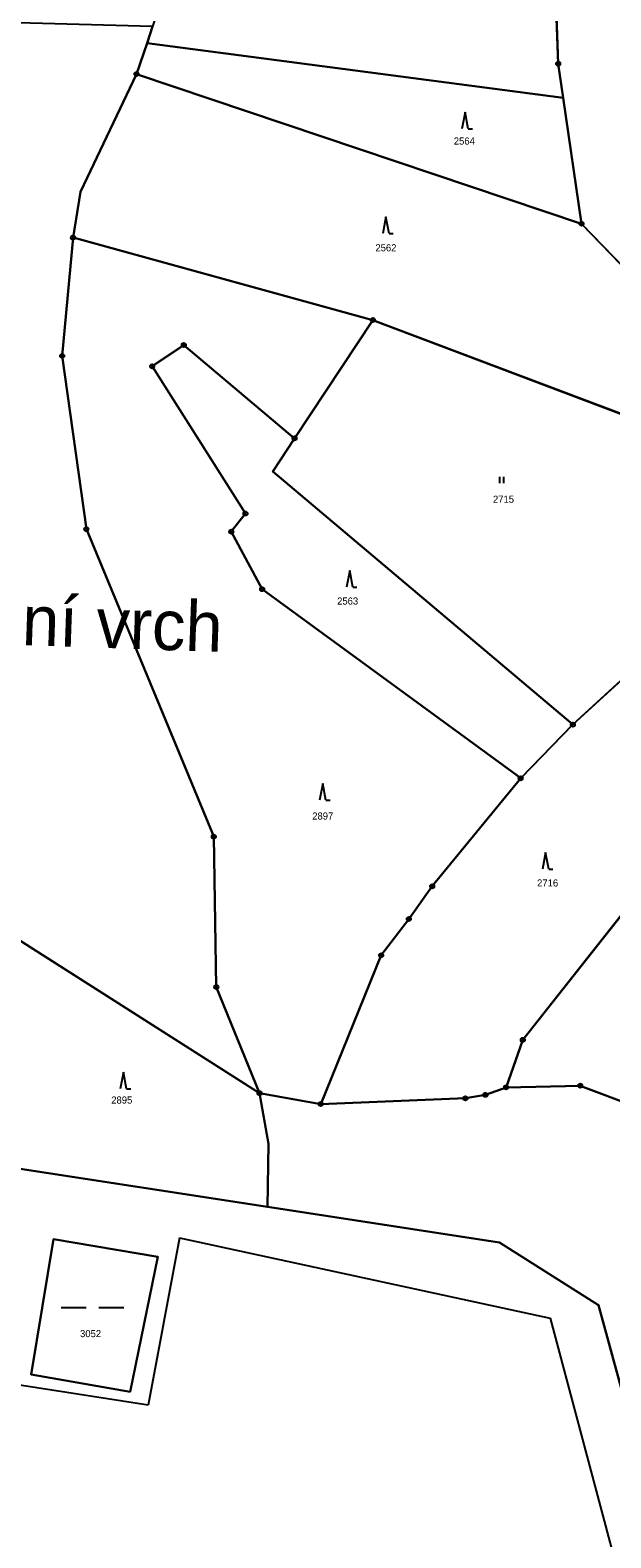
# Model space of a CAD drawing. Extents: x -689422 to -685210, y -987725 to -982160.
# Drawn here: x -687914.3 to -687774.8, y -986923.9 to -986562 of the extents above; entities that cross this region are included whole.
import ezdxf

# ---------------------------------------------------------------- set-up
doc = ezdxf.new("R2010")
doc.units = 0
for name, color, linetype in [('KN_Hranice_parcel', 7, 'Continuous'), ('KN_Hranice_parcel_vnitrni_kresba', 7, 'Continuous'), ('KN_Parcelni cisla', 7, 'Continuous'), ('KN_Polygon parcely', 7, 'Continuous'), ('KN_Popisy_pomistni nazvy', 7, 'Continuous'), ('KN_POZEMKY_LESNI POZEMEK', 7, 'Continuous'), ('KN_POZEMKY_TTP', 7, 'Continuous'), ('KN_POZEMKY_VODNI_PLOCHA', 7, 'Continuous'), ('KN_VYUZITI_10_vodni plocha_nadrz umela', 7, 'Continuous'), ('KN_Značky bodu BP', 7, 'Continuous'), ('KN_Značky kultur', 7, 'Continuous')]:
    doc.layers.add(name, color=color, linetype=linetype)

msp = doc.modelspace()

# ---------------------------------------------------------------- linework, layer by layer
at = {"layer": 'KN_Hranice_parcel'}
for p, q in [((-687884.88, -986561.12), (-687886.23, -986565.1)), ((-687886.23, -986565.1), (-687888.75, -986572.55)), ((-687886.23, -986565.1), (-687786.3, -986578.26)), ((-687781.9, -986608.47), (-687888.75, -986572.55)), ((-687787.49, -986570.08), (-687786.3, -986578.26)), ((-687786.3, -986578.26), (-687781.9, -986608.47)), ((-687781.9, -986608.47), (-687722.74, -986669.66)), ((-687904, -986611.8), (-687832, -986631.6)), ((-687832, -986631.6), (-687850.8, -986660)), ((-687832, -986631.6), (-687755.13, -986660.64)), ((-687783.97, -986728.72), (-687762.96, -986709.43)), ((-687796.5, -986741.6), (-687783.97, -986728.72)), ((-687924.19, -986775.84), (-687859.2, -986817.2)), ((-687844.5, -986819.8), (-687859.2, -986817.2)), ((-687917.71, -986835.19), (-687857.29, -986844.48)), ((-687857.29, -986844.48), (-687801.59, -986853.04))]:
    msp.add_line(p, q, dxfattribs=at)
for points in [[(-687797.83, -986386.92), (-687790.62, -986405.91), (-687786.34, -986436.56), (-687784.88, -986471.18), (-687789.17, -986524.19), (-687787.49, -986570.08)], [(-687888.75, -986572.55), (-687902.18, -986600.85), (-687904, -986611.8)], [(-687859.2, -986817.2), (-687869.6, -986791.7), (-687870.2, -986755.6), (-687900.8, -986681.8), (-687906.6, -986640.2), (-687904, -986611.8)], [(-687850.8, -986660), (-687877.4, -986637.6), (-687885, -986642.7), (-687862.6, -986678.05), (-687866, -986682.4), (-687858.6, -986696.2), (-687796.5, -986741.6)], [(-687850.8, -986660), (-687856.04, -986667.92), (-687783.97, -986728.72)], [(-687796.5, -986741.6), (-687817.75, -986767.54), (-687823.36, -986775.4), (-687830, -986784.1), (-687844.5, -986819.8)], [(-687800, -986815.8), (-687796, -986804.4), (-687745, -986739.8)], [(-687760, -986828.8), (-687769, -986820.4), (-687782.2, -986815.4), (-687800, -986815.8)], [(-687857.29, -986844.48), (-687857.05, -986829.39), (-687859.2, -986817.2)], [(-687800, -986815.8), (-687804.97, -986817.61), (-687809.77, -986818.43), (-687844.5, -986819.8)], [(-687890.28, -986888.85), (-687883.65, -986856.49), (-687908.72, -986852.2), (-687914.04, -986884.71), (-687890.28, -986888.85)], [(-687801.59, -986853.04), (-687777.85, -986868.06), (-687738.9, -987010.24)]]:
    msp.add_lwpolyline(points, dxfattribs=at)
at = {"layer": 'KN_Hranice_parcel_vnitrni_kresba'}
for p, q in [((-687878.47, -986851.93), (-687885.99, -986892.08)), ((-687878.47, -986851.93), (-687789.45, -986871.21)), ((-687789.45, -986871.21), (-687761.64, -986975.47)), ((-687885.99, -986892.08), (-687925.98, -986885.88))]:
    msp.add_line(p, q, dxfattribs=at)
at = {"layer": 'KN_Polygon parcely'}
for points in [[(-687790.62, -986405.91), (-687786.34, -986436.56), (-687784.88, -986471.18), (-687789.17, -986524.19), (-687787.49, -986570.08), (-687786.3, -986578.26), (-687781.9, -986608.47), (-687722.74, -986669.66), (-687718.6, -986669.11), (-687717.65, -986667.57), (-687728.99, -986648.21), (-687730.88, -986571), (-687735.67, -986566.76), (-687746.52, -986430.63), (-687750.35, -986431.59), (-687770.7, -986373.38), (-687759.36, -986370.08), (-687790, -986253.39), (-687797.65, -986255.17), (-687805.09, -986188.05), (-687812.02, -986279.24), (-687801.17, -986347.9), (-687797.83, -986386.92)], [(-687871.04, -986468.74), (-687876.41, -986536.11), (-687884.88, -986561.12), (-687886.23, -986565.1), (-687786.3, -986578.26), (-687787.49, -986570.08), (-687789.17, -986524.19), (-687784.88, -986471.18), (-687786.34, -986436.56), (-687790.62, -986405.91), (-687797.83, -986386.92), (-687864.46, -986388.44), (-687867.38, -986407.55), (-687869.16, -986432.27)], [(-687904, -986611.8), (-687902.18, -986600.85), (-687888.75, -986572.55), (-687886.23, -986565.1), (-687884.88, -986561.12), (-687949.56, -986559.41), (-687948.5, -986613.39), (-687940.02, -986665.46), (-687939.49, -986668.72), (-687976.55, -986661.97), (-688002.05, -986645.15), (-687999.83, -986658.89), (-687996.11, -986675.9), (-687982.65, -986687.78), (-687959.59, -986717.67), (-687931.16, -986761.84), (-687924.19, -986775.84), (-687859.2, -986817.2), (-687869.6, -986791.7), (-687870.2, -986755.6), (-687900.8, -986681.8), (-687906.6, -986640.2)], [(-687886.23, -986565.1), (-687888.75, -986572.55), (-687781.9, -986608.47), (-687786.3, -986578.26)], [(-687888.75, -986572.55), (-687902.18, -986600.85), (-687904, -986611.8), (-687832, -986631.6), (-687755.13, -986660.64), (-687722.74, -986669.66), (-687781.9, -986608.47)], [(-687832, -986631.6), (-687904, -986611.8), (-687906.6, -986640.2), (-687900.8, -986681.8), (-687870.2, -986755.6), (-687869.6, -986791.7), (-687859.2, -986817.2), (-687844.5, -986819.8), (-687830, -986784.1), (-687823.36, -986775.4), (-687817.75, -986767.54), (-687796.5, -986741.6), (-687858.6, -986696.2), (-687866, -986682.4), (-687862.6, -986678.05), (-687885, -986642.7), (-687877.4, -986637.6), (-687850.8, -986660)], [(-687762.96, -986709.43), (-687771.34, -986700.37), (-687771.85, -986686.53), (-687761.77, -986674.42), (-687755.13, -986660.64), (-687832, -986631.6), (-687850.8, -986660), (-687856.04, -986667.92), (-687783.97, -986728.72)], [(-687862.6, -986678.05), (-687866, -986682.4), (-687858.6, -986696.2), (-687796.5, -986741.6), (-687783.97, -986728.72), (-687856.04, -986667.92), (-687850.8, -986660), (-687877.4, -986637.6), (-687885, -986642.7)], [(-687796, -986804.4), (-687745, -986739.8), (-687732.15, -986715.97), (-687762.96, -986709.43), (-687783.97, -986728.72), (-687796.5, -986741.6), (-687817.75, -986767.54), (-687823.36, -986775.4), (-687830, -986784.1), (-687844.5, -986819.8), (-687809.77, -986818.43), (-687804.97, -986817.61), (-687800, -986815.8)], [(-687710.7, -986756.1), (-687745, -986739.8), (-687796, -986804.4), (-687800, -986815.8), (-687782.2, -986815.4), (-687769, -986820.4), (-687760, -986828.8)], [(-687857.29, -986844.48), (-687857.05, -986829.39), (-687859.2, -986817.2), (-687924.19, -986775.84), (-687917.3, -986800.19), (-687916.91, -986829.47), (-687917.71, -986835.19)], [(-687844.5, -986819.8), (-687859.2, -986817.2), (-687857.05, -986829.39), (-687857.29, -986844.48), (-687801.59, -986853.04), (-687777.85, -986868.06), (-687738.9, -987010.24), (-687722.96, -987052.43), (-687720.17, -987051.57), (-687736.81, -987011.46), (-687651.15, -986965.83), (-687665.06, -986948.79), (-687685.35, -986917.93), (-687730.5, -986864.37), (-687744.99, -986846.08), (-687760, -986828.8), (-687769, -986820.4), (-687782.2, -986815.4), (-687800, -986815.8), (-687804.97, -986817.61), (-687809.77, -986818.43)], [(-687890.28, -986888.85), (-687914.04, -986884.71), (-687908.72, -986852.2), (-687883.65, -986856.49)], [(-687890.28, -986888.85), (-687883.65, -986856.49), (-687908.72, -986852.2), (-687914.04, -986884.71)]]:
    msp.add_lwpolyline(points, close=True, dxfattribs=at)
msp.add_lwpolyline([(-687738.9, -987010.24), (-687777.85, -986868.06), (-687801.59, -986853.04), (-687857.29, -986844.48), (-687917.71, -986835.19), (-687921.47, -986834.64), (-688030.54, -986818.6), (-688080.39, -986811.27), (-688085.26, -986813.61), (-688094.78, -986845.97), (-688099.71, -986860.89), (-688113.79, -986903.54), (-688114.98, -986909.18), (-688108.19, -986917.45), (-688106.29, -986919.76), (-688107.71, -986957.91)], dxfattribs=at)
at = {"layer": 'KN_POZEMKY_LESNI POZEMEK'}
for p, q in [((-687787.49, -986570.08), (-687789.17, -986524.19)), ((-687884.88, -986561.12), (-687886.23, -986565.1)), ((-687886.23, -986565.1), (-687888.75, -986572.55)), ((-687888.75, -986572.55), (-687886.23, -986565.1)), ((-687886.23, -986565.1), (-687786.3, -986578.26)), ((-687888.75, -986572.55), (-687902.18, -986600.85)), ((-687902.18, -986600.85), (-687888.75, -986572.55)), ((-687888.75, -986572.55), (-687781.9, -986608.47)), ((-687781.9, -986608.47), (-687888.75, -986572.55)), ((-687786.3, -986578.26), (-687787.49, -986570.08)), ((-687781.9, -986608.47), (-687786.3, -986578.26)), ((-687786.3, -986578.26), (-687781.9, -986608.47)), ((-687902.18, -986600.85), (-687904, -986611.8)), ((-687904, -986611.8), (-687902.18, -986600.85)), ((-687722.74, -986669.66), (-687781.9, -986608.47)), ((-687781.9, -986608.47), (-687722.74, -986669.66)), ((-687904, -986611.8), (-687906.6, -986640.2)), ((-687906.6, -986640.2), (-687904, -986611.8)), ((-687904, -986611.8), (-687832, -986631.6)), ((-687832, -986631.6), (-687904, -986611.8)), ((-687832, -986631.6), (-687850.8, -986660)), ((-687755.13, -986660.64), (-687832, -986631.6)), ((-687877.4, -986637.6), (-687885, -986642.7)), ((-687885, -986642.7), (-687877.4, -986637.6)), ((-687850.8, -986660), (-687877.4, -986637.6)), ((-687877.4, -986637.6), (-687850.8, -986660)), ((-687906.6, -986640.2), (-687900.8, -986681.8)), ((-687900.8, -986681.8), (-687906.6, -986640.2)), ((-687885, -986642.7), (-687862.6, -986678.05)), ((-687862.6, -986678.05), (-687885, -986642.7)), ((-687850.8, -986660), (-687856.04, -986667.92)), ((-687856.04, -986667.92), (-687783.97, -986728.72)), ((-687862.6, -986678.05), (-687866, -986682.4)), ((-687866, -986682.4), (-687862.6, -986678.05)), ((-687900.8, -986681.8), (-687870.2, -986755.6)), ((-687870.2, -986755.6), (-687900.8, -986681.8)), ((-687866, -986682.4), (-687858.6, -986696.2)), ((-687858.6, -986696.2), (-687866, -986682.4)), ((-687858.6, -986696.2), (-687796.5, -986741.6)), ((-687796.5, -986741.6), (-687858.6, -986696.2)), ((-687783.97, -986728.72), (-687762.96, -986709.43)), ((-687783.97, -986728.72), (-687796.5, -986741.6)), ((-687796.5, -986741.6), (-687783.97, -986728.72)), ((-687796.5, -986741.6), (-687817.75, -986767.54)), ((-687817.75, -986767.54), (-687796.5, -986741.6)), ((-687796, -986804.4), (-687745, -986739.8)), ((-687745, -986739.8), (-687796, -986804.4)), ((-687870.2, -986755.6), (-687869.6, -986791.7)), ((-687869.6, -986791.7), (-687870.2, -986755.6)), ((-687817.75, -986767.54), (-687823.36, -986775.4)), ((-687823.36, -986775.4), (-687817.75, -986767.54)), ((-687823.36, -986775.4), (-687830, -986784.1)), ((-687830, -986784.1), (-687823.36, -986775.4)), ((-687859.2, -986817.2), (-687924.19, -986775.84)), ((-687924.19, -986775.84), (-687859.2, -986817.2)), ((-687830, -986784.1), (-687844.5, -986819.8)), ((-687844.5, -986819.8), (-687830, -986784.1)), ((-687869.6, -986791.7), (-687859.2, -986817.2)), ((-687859.2, -986817.2), (-687869.6, -986791.7)), ((-687800, -986815.8), (-687796, -986804.4)), ((-687796, -986804.4), (-687800, -986815.8)), ((-687782.2, -986815.4), (-687800, -986815.8)), ((-687800, -986815.8), (-687782.2, -986815.4)), ((-687769, -986820.4), (-687782.2, -986815.4)), ((-687782.2, -986815.4), (-687769, -986820.4)), ((-687844.5, -986819.8), (-687859.2, -986817.2)), ((-687857.05, -986829.39), (-687859.2, -986817.2)), ((-687859.2, -986817.2), (-687844.5, -986819.8)), ((-687859.2, -986817.2), (-687857.05, -986829.39)), ((-687844.5, -986819.8), (-687809.77, -986818.43)), ((-687809.77, -986818.43), (-687844.5, -986819.8)), ((-687809.77, -986818.43), (-687804.97, -986817.61)), ((-687804.97, -986817.61), (-687809.77, -986818.43)), ((-687804.97, -986817.61), (-687800, -986815.8)), ((-687800, -986815.8), (-687804.97, -986817.61)), ((-687857.29, -986844.48), (-687857.05, -986829.39)), ((-687857.05, -986829.39), (-687857.29, -986844.48)), ((-687917.71, -986835.19), (-687857.29, -986844.48)), ((-687857.29, -986844.48), (-687917.71, -986835.19)), ((-687857.29, -986844.48), (-687801.59, -986853.04)), ((-687801.59, -986853.04), (-687857.29, -986844.48)), ((-687908.72, -986852.2), (-687914.04, -986884.71)), ((-687883.65, -986856.49), (-687908.72, -986852.2)), ((-687801.59, -986853.04), (-687777.85, -986868.06)), ((-687777.85, -986868.06), (-687801.59, -986853.04)), ((-687890.28, -986888.85), (-687883.65, -986856.49)), ((-687777.85, -986868.06), (-687738.9, -987010.24)), ((-687738.9, -987010.24), (-687777.85, -986868.06)), ((-687914.04, -986884.71), (-687890.28, -986888.85))]:
    msp.add_line(p, q, dxfattribs=at)
at = {"layer": 'KN_POZEMKY_TTP'}
for p, q in [((-687789.17, -986524.19), (-687787.49, -986570.08)), ((-687886.23, -986565.1), (-687884.88, -986561.12)), ((-687786.3, -986578.26), (-687886.23, -986565.1)), ((-687787.49, -986570.08), (-687786.3, -986578.26)), ((-687850.8, -986660), (-687832, -986631.6)), ((-687832, -986631.6), (-687755.13, -986660.64)), ((-687856.04, -986667.92), (-687850.8, -986660)), ((-687783.97, -986728.72), (-687856.04, -986667.92)), ((-687762.96, -986709.43), (-687783.97, -986728.72))]:
    msp.add_line(p, q, dxfattribs=at)
at = {"layer": 'KN_POZEMKY_VODNI_PLOCHA'}
for p, q in [((-687914.04, -986884.71), (-687908.72, -986852.2)), ((-687908.72, -986852.2), (-687883.65, -986856.49)), ((-687883.65, -986856.49), (-687890.28, -986888.85)), ((-687890.28, -986888.85), (-687914.04, -986884.71))]:
    msp.add_line(p, q, dxfattribs=at)
at = {"layer": 'KN_VYUZITI_10_vodni plocha_nadrz umela'}
for p, q in [((-687914.04, -986884.71), (-687908.72, -986852.2)), ((-687908.72, -986852.2), (-687883.65, -986856.49)), ((-687883.65, -986856.49), (-687890.28, -986888.85)), ((-687890.28, -986888.85), (-687914.04, -986884.71))]:
    msp.add_line(p, q, dxfattribs=at)
at = {"layer": 'KN_Značky bodu BP'}
for centre, radius in [((-687888.75, -986572.55), 0.5), ((-687888.75, -986572.55), 0.0303), ((-687787.49, -986570.08), 0.5), ((-687787.49, -986570.08), 0.0303), ((-687781.9, -986608.47), 0.5), ((-687781.9, -986608.47), 0.0303), ((-687904, -986611.8), 0.5), ((-687904, -986611.8), 0.0303), ((-687832, -986631.6), 0.5), ((-687832, -986631.6), 0.0303), ((-687877.4, -986637.6), 0.5), ((-687877.4, -986637.6), 0.0303), ((-687906.6, -986640.2), 0.5), ((-687906.6, -986640.2), 0.0303), ((-687885, -986642.7), 0.5), ((-687885, -986642.7), 0.0303), ((-687850.8, -986660), 0.5), ((-687850.8, -986660), 0.0303), ((-687862.6, -986678.05), 0.5), ((-687900.8, -986681.8), 0.5), ((-687862.6, -986678.05), 0.0303), ((-687900.8, -986681.8), 0.0303), ((-687866, -986682.4), 0.5), ((-687866, -986682.4), 0.0303), ((-687858.6, -986696.2), 0.5), ((-687858.6, -986696.2), 0.0303), ((-687783.97, -986728.72), 0.5), ((-687783.97, -986728.72), 0.0303), ((-687796.5, -986741.6), 0.5), ((-687796.5, -986741.6), 0.0303), ((-687870.2, -986755.6), 0.5), ((-687870.2, -986755.6), 0.0303), ((-687817.75, -986767.54), 0.5), ((-687817.75, -986767.54), 0.0303), ((-687823.36, -986775.4), 0.5), ((-687823.36, -986775.4), 0.0303), ((-687830, -986784.1), 0.5), ((-687830, -986784.1), 0.0303), ((-687869.6, -986791.7), 0.5), ((-687869.6, -986791.7), 0.0303), ((-687796, -986804.4), 0.5), ((-687796, -986804.4), 0.0303), ((-687800, -986815.8), 0.5), ((-687782.2, -986815.4), 0.5), ((-687782.2, -986815.4), 0.0303), ((-687859.2, -986817.2), 0.5), ((-687859.2, -986817.2), 0.0303), ((-687809.77, -986818.43), 0.5), ((-687809.77, -986818.43), 0.0303), ((-687804.97, -986817.61), 0.5), ((-687804.97, -986817.61), 0.0303), ((-687800, -986815.8), 0.0303), ((-687844.5, -986819.8), 0.5), ((-687844.5, -986819.8), 0.0303)]:
    msp.add_circle(centre, radius, dxfattribs=at)
at = {"layer": 'KN_Značky kultur'}
for p, q in [((-687809.85, -986581.67), (-687810.6, -986585.67)), ((-687809.1, -986585.67), (-687809.85, -986581.67)), ((-687809.1, -986585.67), (-687808.1, -986585.67)), ((-687828.86, -986606.84), (-687829.61, -986610.84)), ((-687828.11, -986610.84), (-687828.86, -986606.84)), ((-687828.11, -986610.84), (-687827.11, -986610.84)), ((-687801.51, -986670.77), (-687801.51, -986669.27)), ((-687800.51, -986670.77), (-687800.51, -986669.27)), ((-687837.56, -986691.73), (-687838.31, -986695.73)), ((-687836.81, -986695.73), (-687837.56, -986691.73)), ((-687836.81, -986695.73), (-687835.81, -986695.73)), ((-687844.04, -986742.85), (-687844.79, -986746.85)), ((-687843.29, -986746.85), (-687844.04, -986742.85)), ((-687843.29, -986746.85), (-687842.29, -986746.85)), ((-687790.51, -986759.4), (-687791.26, -986763.4)), ((-687789.76, -986763.4), (-687790.51, -986759.4)), ((-687789.76, -986763.4), (-687788.76, -986763.4)), ((-687891.9, -986812.12), (-687892.65, -986816.12)), ((-687891.15, -986816.12), (-687891.9, -986812.12)), ((-687891.15, -986816.12), (-687890.15, -986816.12)), ((-687906.83, -986868.62), (-687900.83, -986868.62)), ((-687897.83, -986868.62), (-687891.83, -986868.62))]:
    msp.add_line(p, q, dxfattribs=at)

# ---------------------------------------------------------------- texts
at = {"layer": 'KN_Parcelni cisla'}
for s, p in [('2564', (-687812.56, -986589.48)), ('2562', (-687831.39, -986615.1)), ('2715', (-687803.16, -986675.46)), ('2563', (-687840.58, -986699.9)), ('2897', (-687846.56, -986751.51)), ('2716', (-687792.56, -986767.58)), ('2895', (-687894.82, -986819.69)), ('3052', (-687902.31, -986875.76))]:
    msp.add_text(s, height=1.7, dxfattribs=at).set_placement(p)
at = {"layer": 'KN_Popisy_pomistni nazvy'}
msp.add_text('Kostelní vrch', height=12, rotation=358, dxfattribs=at).set_placement((-687960.97, -986708.05))

doc.saveas('drawing.dxf')
